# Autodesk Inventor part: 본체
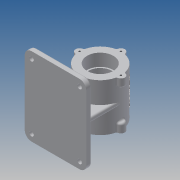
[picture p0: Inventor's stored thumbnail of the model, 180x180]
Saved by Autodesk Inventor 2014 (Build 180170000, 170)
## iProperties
Created: 2015-12
Part Number: 본체
Material: 일반
Document SubType Name: Modeling
Designer: Owner
Density: 1 g/cm^3
Appearance: 기본값
Author: Owner
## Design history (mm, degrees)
sketch "스케치1"
  geometry: C1 r 37 at (0, 0); 1 further point
  constraints: 1 centre point, 1 coincident
  dimensions: "d0" = 74 diameter of C1
extrude "돌출1" new body sketch "스케치1" distance "d1" = 85; taper "d2" = 0 deg
sketch "스케치2"
  geometry: C1 r 37 at (0, 0) reference; C2 r 23.5 at (0, 0)
  constraints: 1 centre point, 1 coincident
  dimensions: "d3" = 47 diameter of C2
extrude "돌출2" cut sketch "스케치2" distance "d4" = 22; taper "d5" = 0 deg
sketch "스케치3"
  geometry: C1 r 37 at (0, 0) reference; C2 r 23.5 at (0, 0)
  constraints: 1 centre point, 1 coincident
  dimensions: "d6" = 47 diameter of C2
extrude "돌출3" cut sketch "스케치3" distance "d7" = 22; taper "d8" = 0 deg
sketch "스케치4"
  geometry: C1 r 23.5 at (0, 0) reference; C2 r 21 at (0, 0)
  constraints: 1 centre point, 1 coincident
  dimensions: "d9" = 42 diameter of C2
extrude "돌출4" cut sketch "스케치4" distance "d10" = 41; taper "d11" = 0 deg
sketch "스케치5"
  geometry: C1 r 7 at (0, 37); C2 r 7 at (-37, 0); C3 r 7 at (0, -37); C4 r 7 at (37, 0); A1 r 37 centre (0, 0) between (0, 37) and (-37, 0) reference
  constraints: 4 centre point, 4 point on circle
  dimensions: "d12" = 14 diameter of C1; "d13" = 14 diameter of C4; "d14" = 14 diameter of C2; "d15" = 14 diameter of C3
extrude "돌출5" join sketch "스케치5" distance "d16" = 15; taper "d17" = 0 deg
sketch "스케치6"
  geometry: C1 r 7 at (0, 37); C2 r 7 at (-37, 0); C3 r 7 at (0, -37); C4 r 7 at (37, 0); A1 r 37 centre (0, 0) between (0, 37) and (-37, 0) reference
  constraints: 4 centre point, 4 point on circle
  dimensions: "d18" = 14 diameter of C1; "d19" = 14 diameter of C4; "d20" = 14 diameter of C3; "d21" = 14 diameter of C2
extrude "돌출6" join sketch "스케치6" distance "d22" = 15; taper "d23" = 0 deg
sketch "스케치7"
  geometry: A1 r 7 centre (0, 37) between (6.969, 36.338) and (-6.969, 36.338) reference; A2 r 7 centre (-37, 0) between (-36.338, 6.969) and (-36.338, -6.969) reference; A3 r 7 centre (0, -37) between (-6.969, -36.338) and (6.969, -36.338) reference; A4 r 7 centre (37, 0) between (36.338, -6.969) and (36.338, 6.969) reference; 4 further points
  constraints: 4 coincident
hole "구멍1" sketch "스케치7" at (0, 37), (-37, 0), (0, -37), (37, 0) diameter "d24" = 3.242; stored, may be unused: countersink angle "d28" = 90 deg, drill point angle "d30" = 118 deg; dims "d25" = 9, "d26" = 4, "d27" = 2, "d29" = 11
sketch "스케치8"
  geometry: C1 r 1.621 at (0, 37) reference; C2 r 1.621 at (-37, 0) reference; C3 r 1.621 at (37, 0) reference; A1 r 7 centre (0, -37) between (-6.969, -36.338) and (6.969, -36.338) reference; 4 further points
  constraints: 4 coincident
hole "구멍2" sketch "스케치8" at (0, 37), (-37, 0), (0, -37), (37, 0) diameter "d31" = 3.242; stored, may be unused: countersink angle "d35" = 90 deg, drill point angle "d37" = 118 deg; dims "d32" = 9, "d33" = 4, "d34" = 2, "d36" = 11
node "작업 평면1"
sketch "스케치9"
  geometry: L1 (0, 0)-(0, -17.5); L2 (-55, 122.5)-(55, 122.5); L3 (55, 122.5)-(55, -17.5); L4 (55, -17.5)-(-55, -17.5); L5 (-55, -17.5)-(-55, 122.5)
  constraints: 10 end point, 2 parallel, 1 horizontal, 1 midpoint, 1 perpendicular, 1 vertical
  dimensions: "d40" = 17.5 distance of L1.end L1.start; "d41" = 110 distance between parallel lines of L3 L5; "d42" = 140 distance between parallel lines of L4 L2
extrude "돌출7" join sketch "스케치9" distance "d43" = 10; taper "d44" = 0 deg
fillet "모깎기1" dims "d45" = 12
sketch "스케치10"
  geometry: C1 r 4 at (-43, -110.5); C2 r 4 at (43, -110.5); C3 r 4 at (43, 5.5); C4 r 4 at (-43, 5.5); A1 r 12 centre (-43, -110.5) between (-55, -110.5) and (-43, -122.5) reference; A2 r 12 centre (43, -110.5) between (43, -122.5) and (55, -110.5) reference; A3 r 12 centre (43, 5.5) between (55, 5.5) and (43, 17.5) reference; A4 r 12 centre (-43, 5.5) between (-43, 17.5) and (-55, 5.5) reference; 1 further point
  constraints: 4 centre point, 4 coincident
  dimensions: "d46" = 8 diameter of C1; "d47" = 8 diameter of C2; "d48" = 8 diameter of C3; "d49" = 8 diameter of C4
extrude "돌출8" cut sketch "스케치10" stored distance "d50" = 10; taper "d51" = 0 deg
node "작업 평면2"
sketch "스케치11"
  geometry: L1 (-80, 122.5)-(-70, 122.5) reference; L2 (-70, 122.5)-(-70, -17.5) reference; L3 (-70, -17.5)-(-80, -17.5) reference; L4 (-80, -17.5)-(-80, 122.5) reference; L5 (23.5, 63)-(23.5, 85) reference; L6 (23.5, 85)-(35.379, 85) reference; L7 (35.379, 85)-(35.379, 74) reference; L8 (35.379, 74)-(37, 73.026) reference; L9 (37, 73.026)-(38.621, 74) reference; L10 (38.621, 74)-(38.621, 85) reference; L11 (38.621, 85)-(44, 85) reference; L12 (44, 85)-(44, 70) reference; L13 (44, 70)-(37, 70) reference; L14 (37, 70)-(37, 15) reference; L15 (37, 15)-(44, 15) reference; L16 (44, 15)-(44, 0) reference; L17 (44, 0)-(38.621, 0) reference; L18 (38.621, 0)-(38.621, 11) reference; L19 (38.621, 11)-(37, 11.974) reference; L20 (37, 11.974)-(35.379, 11) reference; L21 (35.379, 11)-(35.379, 0) reference; L22 (35.379, 0)-(23.5, 0) reference; L23 (23.5, 0)-(23.5, 22) reference; L24 (23.5, 22)-(21, 22) reference; L25 (21, 22)-(21, 63) reference; L26 (21, 63)-(23.5, 63) reference; L27 (-23.5, 85)-(-23.5, 63) reference; L28 (-23.5, 63)-(-21, 63) reference; L29 (-21, 63)-(-21, 22) reference; L30 (-21, 22)-(-23.5, 22) reference; L31 (-23.5, 22)-(-23.5, 0) reference; L32 (-23.5, 0)-(-35.379, 0) reference; L33 (-35.379, 0)-(-35.379, 11) reference; L34 (-35.379, 11)-(-37, 11.974) reference; L35 (-37, 11.974)-(-38.621, 11) reference; L36 (-38.621, 11)-(-38.621, 0) reference; L37 (-38.621, 0)-(-44, 0) reference; L38 (-44, 0)-(-44, 15) reference; L39 (-44, 15)-(-37, 15) reference; L40 (-37, 15)-(-37, 70) reference; L41 (-37, 70)-(-44, 70) reference; L42 (-44, 70)-(-44, 85) reference; L43 (-44, 85)-(-38.621, 85) reference; L44 (-38.621, 85)-(-38.621, 74) reference; L45 (-38.621, 74)-(-37, 73.026) reference; L46 (-37, 73.026)-(-35.379, 74) reference; L47 (-35.379, 74)-(-35.379, 85) reference; L48 (-35.379, 85)-(-23.5, 85) reference; L49 (37, 42.5)-(-70, 42.5); L50 (-70, 42.5)-(-70, 67.5); L51 (-70, -5.5)-(-70, 110.5) reference; L52 (-70, 42.5)-(-70, 17.5); L53 (-70, 67.5)-(-37, 63.448); L54 (-70, 17.5)-(-37, 21.552); 1 further point
  constraints: 10 end point, 5 point on line, 1 midpoint, 1 parallel
  dimensions: "d52" = 42.5 distance from line of L49 L10.end (derived); "d53" = 25 distance of L49.end L50.end; "d54" = 25 distance of L49.end L52.end; "d55" = 97 deg angle of L2 L53; "d56" = 97 deg angle of L2 L54
extrude "돌출9" join sketch "스케치11" stored distance "d57" = 12; taper "d58" = 0 deg
node "작업 평면3"
sketch "스케치12"
  geometry: L1 (55, -80)-(-55, -80) reference; L2 (-55, -80)-(-55, -70) reference; L3 (-55, -70)-(-6, -70) reference; L4 (-6, -70)-(-6, -37) reference; L5 (-6, -37)-(0, -37) reference; L6 (0, -37)-(6, -37) reference; L7 (6, -37)-(6, -70) reference; L8 (6, -70)-(55, -70) reference; L9 (55, -70)-(55, -80) reference; L10 (37, 0)-(37, -70); L11 (-37, 0)-(-37, -70); L12 (-37, -70)-(37, -70); C1 r 21 at (0, 0) reference; C2 r 1.621 at (37, 0) reference; A1 r 37 centre (0, 0) between (0, -37) and (36.338, -6.969) reference; A2 r 37 centre (0, 0) between (36.338, -6.969) and (36.338, 6.969) reference; 1 further point
  constraints: 6 end point, 3 tangent, 2 parallel, 2 point on line, 1 collinear, 1 point on circle
extrude "돌출10" join sketch "스케치12" stored distance "d59" = 8; taper "d60" = 0 deg
sketch "스케치13"
  geometry: L1 (55, -80)-(-55, -80) reference; L2 (-55, -80)-(-55, -70) reference; L3 (-55, -70)-(-37, -70) reference; L4 (-37, -70)-(-37, 0) reference; L5 (0, -37)-(6, -37) reference; L6 (6, -37)-(6, -70) reference; L7 (6, -70)-(55, -70) reference; L8 (55, -70)-(55, -80) reference; L9 (37, 0)-(37, -70); C1 r 21 at (0, 0) reference; A1 r 37 centre (0, 0) between (0, -37) and (-37, 0) reference; 1 further point
  constraints: 2 end point, 1 parallel, 1 point on circle, 1 point on line, 1 tangent
extrude "돌출11" join sketch "스케치13" stored distance "d61" = 8; taper "d62" = 0 deg
fillet "모깎기2" dims "d63" = 3
fillet "모깎기3" dims "d64" = 3
fillet "모깎기4" dims "d65" = 3
fillet "모깎기5" dims "d66" = 3
node "작업 평면5"
  node "작업 평면4"
sketch "스케치14"
  geometry: L1 (18.921, 85)-(-18.921, 85) reference; L2 (-18.921, 0)-(18.921, 0) reference; L3 (-21.213, 66.837)-(-21.213, 17.062); L4 (-21.213, 17.062)-(21.213, 17.062); L5 (21.213, 17.062)-(21.213, 66.837); L6 (21.213, 66.837)-(-21.213, 66.837); L7 (0, 0)-(0, 85); L8 (0, 66.837)-(0, 17.062); L9 (-21.213, 41.5)-(26.163, 41.5) reference; L10 (-21.213, 41.5)-(21.213, 41.5); 2 further points
  constraints: 6 end point, 5 midpoint, 4 point on line, 2 vertical alignment, 2 other
feature "엠보싱1" sketch "스케치14" dims "d68" = 0.5, "d69" = 0
node "솔리드1"
node "절단 모서리 투영1"
node "절단 모서리 투영2"
node "절단 모서리 투영3"
other parameters: "d67" = -45 deg
